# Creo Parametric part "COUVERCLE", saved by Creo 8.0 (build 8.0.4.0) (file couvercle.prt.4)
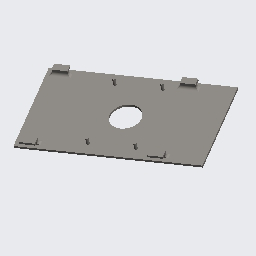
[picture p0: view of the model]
Materials in the file: FR_ACIER_E335

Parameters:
  DESIGNATION = "COMPOSANT CREO"
  PRENOM_DESSINATEUR = ")"
  MATIERE = "FR_ACIER_E335"
  DESSINATEUR = ": - )"
  PTC_MATERIAL_NAME = "FR_ACIER_E335"
  DESCRIPTION = "Concu a l'INSA de Strasbourg"
  VERSION_CREATION = "CREO 8.0"
  MATERIAL = "FR_ACIER_E335"
  DESIGNER_FIRST_NAME = ")"
  DESIGNER_NAME = ":"
  DESIGNER = ": - )"
  DESIGN_RELEASE = "CREO 8.0"
  PTC_MASTER_MATERIAL = "FR_ACIER_E335"
  NORME = "ACIER_A60"

Other parameters: MASSE, VOLUME, MASS, SURF_AREA, XCOG, YCOG, ZCOG, THERM_EXPANSION_REF_TEMPERATURE, STRESS_LIMIT_FOR_TENSION, STRESS_LIMIT_FOR_SHEAR, D21, D22

Created from: FR_MMNS_PIECE_SOLIDE.PRT

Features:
  1. datum plane "PRT_FACE"
  2. datum plane "PRT_DESSUS"
  3. datum plane "PRT_DROITE"
  4. coordinate system
  5. datum point "CDG"
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
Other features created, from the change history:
  planar section "ZONE1-SECTION"
  extrusion "Extrusion 1"
  datum plane "DTM1"
  extrusion "Extrusion 2"
  round "Arrondi 1"
  mirror "Symetrie 1"
  extrusion "Extrusion 2 (2)"
  round "Arrondi 1 (2)"
  mirror "Symetrie 2"
  extrusion "Extrusion 2 (3)"
  round "Arrondi 1 (3)"
  extrusion "Extrusion 2 (4)"
  round "Arrondi 1 (4)"
  datum plane "DTM2"
  extrusion "Extrusion 4"
  extruded cut "Extrusion 5"

Other named items: PRT_REP, MASS_PROP, LOCAL_GROUP, LOCAL_GROUP_1, LOCAL_GROUP_2, LOCAL_GROUP_3, PROP_MASSIQUES, CENTRE_GRAVITE, FACE, ARRIERE, DESSUS, DESSOUS, DROITE, GAUCHE, ANNOT_LAYER_STATE0001, ANNOT_LAYER_STATE0002, ANNOT_LAYER_STATE0003, ANNOT_LAYER_STATE0004, ANNOT_LAYER_STATE0005, ANNOT_LAYER_STATE0006

Notes: MASSE :  | 0,093 | VOLUME :  | 11,812 |  cm3 | Centre de Gravité | X :  | -0,456 | Y :  | 0,601 | Z :  |   mm

Surfaces: 41 plane, 17 cylinder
